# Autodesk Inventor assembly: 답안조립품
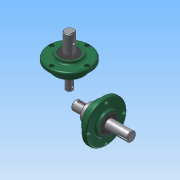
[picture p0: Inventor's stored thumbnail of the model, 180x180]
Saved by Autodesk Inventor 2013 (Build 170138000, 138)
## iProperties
Created: 2016-09
Part Number: 답안조립품
Document SubType Name: Assembly
Designer: Administrator
Author: Administrator
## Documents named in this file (9)
- C:\Users\Administrator\Desktop\460908V1005\답안조립품.iam
- C:\Users\Administrator\Desktop\460908V1005\본체.ipt
- C:\Users\Administrator\Desktop\460908V1005\베어링 6203.ipt
- C:\Users\Administrator\Desktop\460908V1005\커버.ipt
- C:\Users\Administrator\Desktop\460908V1005\오일실 17 32 8.ipt
- C:\Users\Administrator\Desktop\460908V1005\메인 축.ipt
- 메인 축.ipt
- C:\Users\Administrator\Desktop\460908V1005\서브 축.ipt
- 서브 축.ipt
